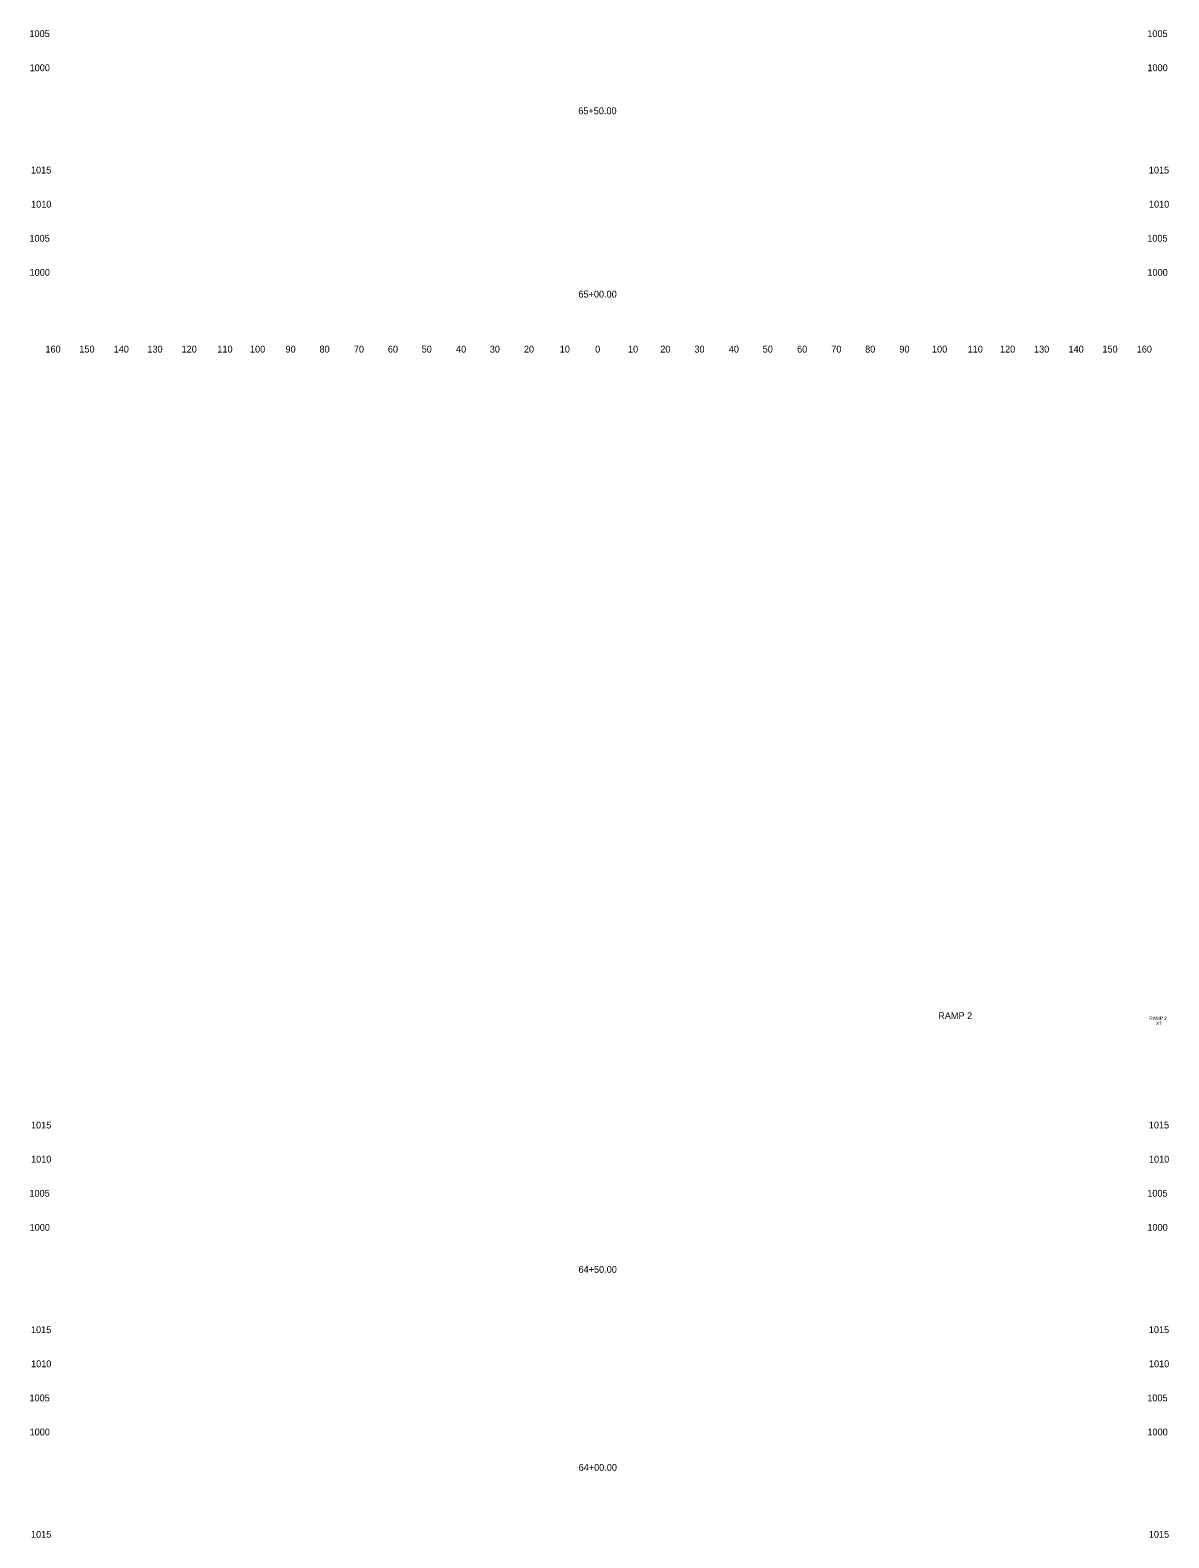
# Model space of a CAD drawing. Extents: x 4994 to 5328, y 4997 to 8804.
# Drawn here: x 4993.6 to 5327.5, y 7450 to 7892 of the extents above; entities that cross this region are included whole.
import ezdxf

# ---------------------------------------------------------------- set-up
doc = ezdxf.new("R2010")
doc.units = 0
for name, color, linetype in [('RD_SHT_ID', 7, 'Continuous'), ('RD_XS_TX_Offset', 7, 'Continuous'), ('RD_XS_TX_Station', 7, 'Continuous')]:
    doc.layers.add(name, color=color, linetype=linetype)

msp = doc.modelspace()

# ---------------------------------------------------------------- texts
at = {"layer": 'RD_SHT_ID'}
for s, height, p in [('RAMP 2', 2, (5259.89, 7602.06)), ('RAMP 2', 1, (5321.78, 7601.8)), ('X7', 1, (5323.74, 7600.3))]:
    msp.add_text(s, height=height, dxfattribs=at).set_placement(p)
at = {"layer": 'RD_XS_TX_Offset'}
for s, p in [('1005', (4993.4, 7890)), ('1005', (5321.2, 7890)), ('1000', (4993.44, 7880)), ('1000', (5321.24, 7880)), ('1015', (4993.85, 7850)), ('1015', (5321.65, 7850)), ('1010', (4993.88, 7840)), ('1010', (5321.68, 7840)), ('1005', (4993.4, 7830)), ('1005', (5321.2, 7830)), ('1000', (4993.44, 7820)), ('1000', (5321.24, 7820)), ('160', (4998.1, 7797.5)), ('150', (5008.04, 7797.5)), ('140', (5018.1, 7797.5)), ('130', (5027.99, 7797.5)), ('120', (5038.01, 7797.5)), ('110', (5048.51, 7797.5)), ('100', (5058.07, 7797.5)), ('90', (5068.5, 7797.5)), ('80', (5078.46, 7797.5)), ('70', (5088.54, 7797.5)), ('60', (5098.5, 7797.5)), ('50', (5108.43, 7797.5)), ('40', (5118.5, 7797.5)), ('30', (5128.39, 7797.5)), ('20', (5138.4, 7797.5)), ('10', (5148.91, 7797.5)), ('0', (5159.3, 7797.5)), ('0', (5159.3, 7797.5)), ('10', (5168.91, 7797.5)), ('20', (5178.4, 7797.5)), ('30', (5188.39, 7797.5)), ('40', (5198.5, 7797.5)), ('50', (5208.43, 7797.5)), ('60', (5218.5, 7797.5)), ('70', (5228.54, 7797.5)), ('80', (5238.46, 7797.5)), ('90', (5248.5, 7797.5)), ('100', (5258.07, 7797.5)), ('110', (5268.51, 7797.5)), ('120', (5278.01, 7797.5)), ('130', (5287.99, 7797.5)), ('140', (5298.1, 7797.5)), ('150', (5308.04, 7797.5)), ('160', (5318.1, 7797.5)), ('1015', (4993.85, 7570)), ('1015', (5321.65, 7570)), ('1010', (4993.88, 7560)), ('1010', (5321.68, 7560)), ('1005', (4993.4, 7550)), ('1005', (5321.2, 7550)), ('1000', (4993.44, 7540)), ('1000', (5321.24, 7540)), ('1015', (4993.85, 7510)), ('1015', (5321.65, 7510)), ('1010', (4993.88, 7500)), ('1010', (5321.68, 7500)), ('1005', (4993.4, 7490)), ('1005', (5321.2, 7490)), ('1000', (4993.44, 7480)), ('1000', (5321.24, 7480)), ('1015', (4993.85, 7450)), ('1015', (5321.65, 7450))]:
    msp.add_text(s, height=2, dxfattribs=at).set_placement(p)
at = {"layer": 'RD_XS_TX_Station'}
for s, p in [('65+50.00', (5154.35, 7867.38)), ('65+00.00', (5154.39, 7813.63)), ('64+50.00', (5154.42, 7527.68)), ('64+00.00', (5154.45, 7469.62))]:
    msp.add_text(s, height=2, dxfattribs=at).set_placement(p)

doc.saveas('drawing.dxf')
